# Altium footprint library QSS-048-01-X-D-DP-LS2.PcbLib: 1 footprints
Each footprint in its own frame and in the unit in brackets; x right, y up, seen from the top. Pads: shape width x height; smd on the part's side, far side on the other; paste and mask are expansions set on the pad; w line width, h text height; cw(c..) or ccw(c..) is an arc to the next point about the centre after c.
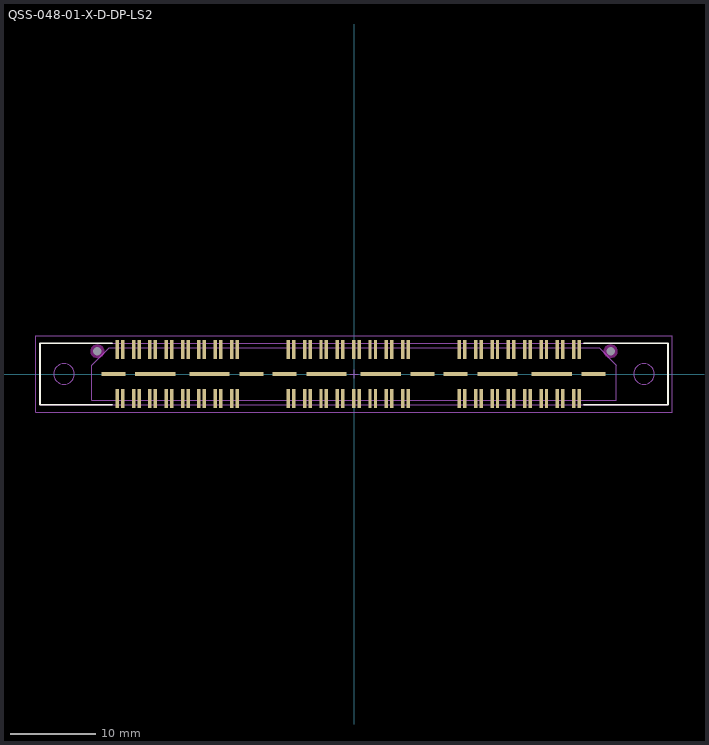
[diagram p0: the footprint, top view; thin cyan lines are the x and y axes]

## QSS-048-01-X-D-DP-LS2 [mm] "0.635mm pitch, 48 pin, high speed socket assembly; differential pair array"
height 3.43
pads (110):
  rect 0.4x2.25 smd mask+0: 1(-27.68,-2.865) 2(-27.68,2.865) 3(-27.04,-2.865) 4(-27.04,2.865) 5(-25.77,-2.865) 6(-25.77,2.865) 7(-25.13,-2.865) 8(-25.13,2.865) 9(-23.86,-2.865) 10(-23.86,2.865) 11(-23.22,-2.865) 12(-23.22,2.865) 13(-21.95,-2.865) 14(-21.95,2.865) 15(-21.31,-2.865) 16(-21.31,2.865) 17(-20.04,-2.865) 18(-20.04,2.865) 19(-19.4,-2.865) 20(-19.4,2.865) 21(-18.13,-2.865) 22(-18.13,2.865) 23(-17.49,-2.865) 24(-17.49,2.865) 25(-16.22,-2.865) 26(-16.22,2.865) 27(-15.58,-2.865) 28(-15.58,2.865) 29(-14.31,-2.865) 30(-14.31,2.865) 31(-13.67,-2.865) 32(-13.67,2.865) 33(-7.68,-2.865) 34(-7.68,2.865) 35(-7.04,-2.865) 36(-7.04,2.865) 37(-5.77,-2.865) 38(-5.77,2.865) 39(-5.13,-2.865) 40(-5.13,2.865) 41(-3.86,-2.865) 42(-3.86,2.865) 43(-3.22,-2.865) 44(-3.22,2.865) 45(-1.95,-2.865) 46(-1.95,2.865) 47(-1.31,-2.865) 48(-1.31,2.865) 49(-0.04,-2.865) 50(-0.04,2.865) 51(0.6,-2.865) 52(0.6,2.865) 53(1.87,-2.865) 54(1.87,2.865) 55(2.51,-2.865) 56(2.51,2.865) 57(3.78,-2.865) 58(3.78,2.865) 59(4.42,-2.865) 60(4.42,2.865) 61(5.69,-2.865) 62(5.69,2.865) 63(6.33,-2.865) 64(6.33,2.865) 65(12.32,-2.865) 66(12.32,2.865) 67(12.96,-2.865) 68(12.96,2.865) 69(14.23,-2.865) 70(14.23,2.865) 71(14.87,-2.865) 72(14.87,2.865) 73(16.14,-2.865) 74(16.14,2.865) 75(16.78,-2.865) 76(16.78,2.865) 77(18.05,-2.865) 78(18.05,2.865) 79(18.69,-2.865) 80(18.69,2.865) 81(19.96,-2.865) 82(19.96,2.865) 83(20.6,-2.865) 84(20.6,2.865) 85(21.87,-2.865) 86(21.87,2.865) 87(22.51,-2.865) 88(22.51,2.865) 89(23.78,-2.865) 90(23.78,2.865) 91(24.42,-2.865) 92(24.42,2.865) 93(25.69,-2.865) 94(25.69,2.865) 95(26.33,-2.865) 96(26.33,2.865)
  rect 2.8x0.45 smd mask+0: 97(-28.12,0) 100(-11.99,0) 101(-8.12,0) 104(8.01,0) 105(11.88,0) 108(28.01,0)
  rect 4.7x0.45 smd mask+0: 98(-23.23,0) 99(-16.88,0) 102(-3.23,0) 103(3.12,0) 106(16.77,0) 107(23.12,0)
  round 0.5 hole 1 unplated mask+0: 109(-30,2.655) 110(30,2.655)
Top Overlay:
  lines w0.2: -28.3,-3.6 -36.7,-3.6 -36.7,3.6 -28.3,3.6 ; 26.9,-3.6 36.7,-3.6 36.7,3.6 26.9,3.6
Keep-Out Layer:
  pour cut-out: 30.807,2.655 30.779,2.864 30.699,3.058 30.571,3.226 30.403,3.354 30.209,3.434 30,3.462 29.791,3.434 29.597,3.354 29.429,3.226 29.301,3.058 29.221,2.864 29.193,2.655 29.221,2.446 29.301,2.252 29.429,2.084 29.597,1.956 29.791,1.876 30,1.848 30.209,1.876 30.403,1.956 30.571,2.084 30.699,2.252 30.779,2.446
  pour cut-out: -29.193,2.655 -29.221,2.864 -29.301,3.058 -29.429,3.226 -29.597,3.354 -29.791,3.434 -30,3.462 -30.209,3.434 -30.403,3.354 -30.571,3.226 -30.699,3.058 -30.779,2.864 -30.807,2.655 -30.779,2.446 -30.699,2.252 -30.571,2.084 -30.403,1.956 -30.209,1.876 -30,1.848 -29.791,1.876 -29.597,1.956 -29.429,2.084 -29.301,2.252 -29.221,2.446
Mechanical 12:
  lines w0.001: -36.7,-3.6 -36.7,3.6 36.7,3.6 36.7,-3.6 -36.7,-3.6
Mechanical 13:
  circle w0.1: c33.9,0 r1.2
  circle w0.1: c-33.9,0 r1.2
  lines w0.1: -36.7,-3.6 -36.7,3.6 36.7,3.6 36.7,-3.6 -36.7,-3.6 ; -30.65,-3.05 -30.65,1.05 -28.64,3.05 28.65,3.05 30.65,1.05 30.65,-3.05 -30.65,-3.05
  text ".Designator" at 0.254,0.254 h1.52
Mechanical 15:
  lines w0.05: -0.5,0 0.5,0 ; 0,-0.5 0,0.5 ; -37.2,-4.5 -37.2,4.5 37.2,4.5 37.2,-4.5 -37.2,-4.5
